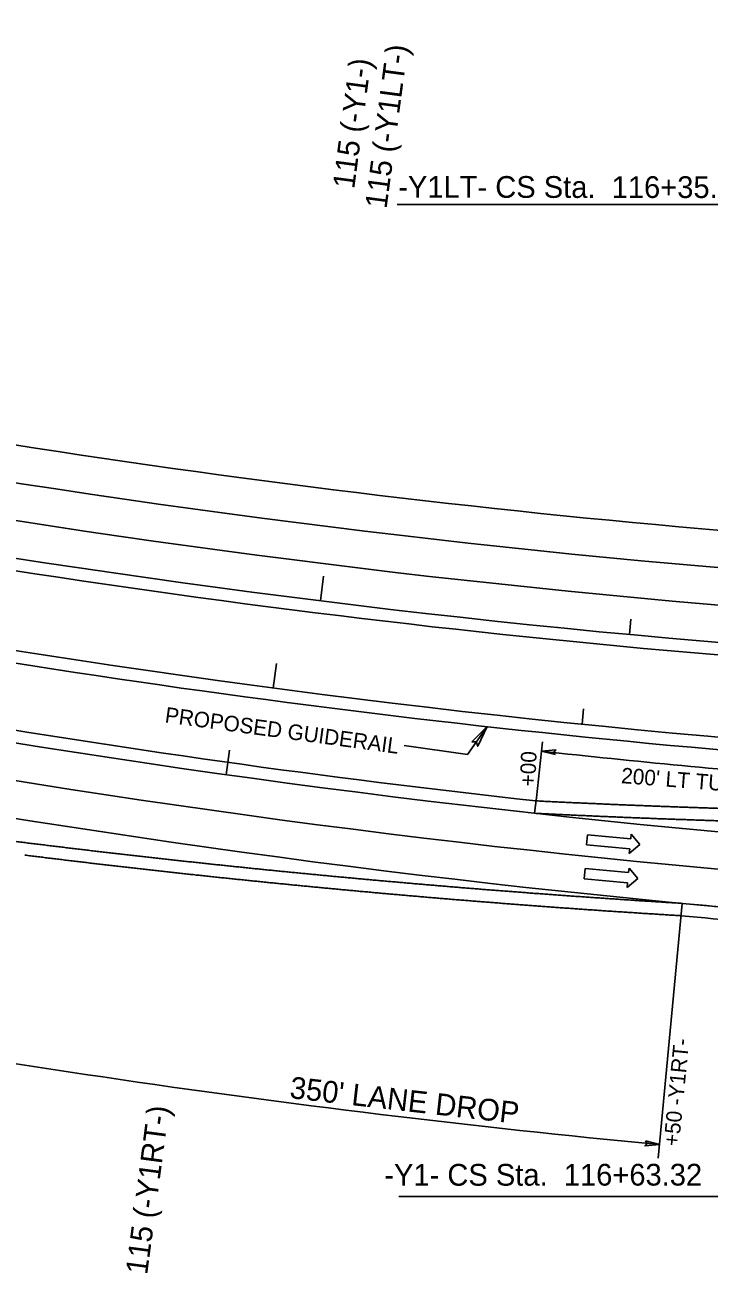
# Model space of a CAD drawing. Extents: x 2389694 to 2405615, y 547005 to 573532.
# Drawn here: x 2399293 to 2399513, y 552256.4 to 552658.1 of the extents above; entities that cross this region are included whole.
import ezdxf

# ---------------------------------------------------------------- set-up
doc = ezdxf.new("R2010")
doc.units = 0
for name, color, linetype in [('Old_Level_11', 7, 'Continuous'), ('Old_Level_22', 7, 'Continuous'), ('Prop Cable Guiderail Double Face', 7, 'Continuous'), ('Prop Dimension', 7, 'Continuous'), ('Prop Dimension Text', 7, 'Continuous'), ('Prop DSN Text', 7, 'Continuous'), ('Prop EOT', 7, 'Continuous'), ('Prop Horizontal Alignment', 7, 'Continuous'), ('Prop Horizontal Alignment Curve and Spiral Data', 7, 'Continuous'), ('Prop Horizontal Alignment Tick Large', 7, 'Continuous'), ('Prop Horizontal Alignment Tick Small', 7, 'Continuous'), ('Prop Lane Arrow Through CELL', 7, 'Continuous'), ('Prop Lane Lines', 7, 'Continuous')]:
    doc.layers.add(name, color=color, linetype=linetype)

# ---------------------------------------------------------------- blocks, each defined once
blk = doc.blocks.new('TERM')
at = {"layer": 'Old_Level_11'}
blk.add_lwpolyline([(-0.01375, 0.00225), (0, 0), (-0.01375, -0.0025), (-0.012, 0)], close=True, dxfattribs=at)

msp = doc.modelspace()

# ---------------------------------------------------------------- linework, layer by layer
at = {"layer": 'Prop Cable Guiderail Double Face'}
msp.add_arc((2399806.57, 555716.05), 3304, 257.63644, 265.28379, dxfattribs=at)
at = {"layer": 'Prop Dimension'}
for p, q in [((2399457.49, 552409.35), (2399459.48, 552427.43)), ((2399504.41, 552375.4), (2399496.65, 552293.39))]:
    msp.add_line(p, q, dxfattribs=at)
for points in [[(2399463.56, 552423.25), (2399459.14, 552424.39), (2399463.72, 552424.81), (2399463.08, 552424.06)], [(2399492.64, 552298.92), (2399497.06, 552297.77), (2399492.49, 552297.35), (2399493.12, 552298.1)]]:
    msp.add_lwpolyline(points, close=True, dxfattribs=at)
for radius, start, end in [(3302.88, 263.72437, 265.30001), (3424.97, 258.5517, 264.5865)]:
    msp.add_arc((2399820.18, 555707.47), radius, start, end, dxfattribs=at)
at = {"layer": 'Prop DSN Text'}
for p, q in [((2399435.38, 552423.31), (2399441.62, 552432.29)), ((2399414.97, 552426.15), (2399435.38, 552423.31))]:
    msp.add_line(p, q, dxfattribs=at)
at = {"layer": 'Prop EOT'}
for centre, radius, start, end in [((2399792.96, 555724.63), 3253, 240.16192, 265.26734), ((2399792.96, 555724.63), 3241, 256.84167, 265.26734), ((2399792.96, 555724.63), 3281, 256.78262, 265.26734), ((2399820.18, 555707.47), 3319, 256.69858, 263.72436), ((2399820.18, 555707.47), 3347, 264.58646, 265.30001), ((2399820.18, 555707.47), 3351, 264.58646, 265.30001)]:
    msp.add_arc(centre, radius, start, end, dxfattribs=at)
for points in [[(2399457.14, 552408.38), (2399458.04, 552408.34), (2399458.94, 552408.29), (2399459.84, 552408.25), (2399460.74, 552408.2), (2399461.64, 552408.16), (2399462.54, 552408.12), (2399463.44, 552408.07), (2399464.34, 552408.03), (2399465.24, 552407.99), (2399466.14, 552407.94), (2399467.04, 552407.9), (2399467.94, 552407.86), (2399468.84, 552407.82), (2399469.74, 552407.78), (2399470.64, 552407.74), (2399471.54, 552407.7), (2399472.45, 552407.65), (2399473.35, 552407.61), (2399474.25, 552407.57), (2399475.15, 552407.53), (2399476.04, 552407.5), (2399476.94, 552407.46), (2399477.84, 552407.42), (2399478.74, 552407.38), (2399479.64, 552407.34), (2399480.54, 552407.3), (2399481.44, 552407.26), (2399482.35, 552407.22), (2399483.25, 552407.19), (2399484.15, 552407.15), (2399485.05, 552407.11), (2399485.95, 552407.07), (2399486.85, 552407.04), (2399487.75, 552407), (2399488.65, 552406.97), (2399489.54, 552406.93), (2399490.44, 552406.89), (2399491.34, 552406.86), (2399492.25, 552406.82), (2399493.15, 552406.79), (2399494.05, 552406.75), (2399494.95, 552406.72), (2399495.85, 552406.68), (2399496.75, 552406.65), (2399497.65, 552406.62), (2399498.55, 552406.58), (2399499.45, 552406.55), (2399500.35, 552406.52), (2399501.25, 552406.48), (2399502.16, 552406.45), (2399503.05, 552406.42), (2399503.95, 552406.39), (2399504.85, 552406.36), (2399505.75, 552406.32), (2399506.65, 552406.29), (2399507.55, 552406.26), (2399508.45, 552406.23), (2399509.35, 552406.2), (2399510.25, 552406.17), (2399511.15, 552406.14), (2399512.05, 552406.11), (2399512.96, 552406.08), (2399513.85, 552406.05), (2399514.75, 552406.02), (2399515.65, 552405.99), (2399516.55, 552405.96), (2399517.45, 552405.94), (2399518.35, 552405.91), (2399519.25, 552405.88), (2399520.15, 552405.85), (2399521.05, 552405.83), (2399521.95, 552405.8), (2399522.86, 552405.77), (2399523.75, 552405.74)], [(2399223.4, 552404.35), (2399224.35, 552404.21), (2399225.29, 552404.08), (2399226.24, 552403.94), (2399227.18, 552403.8), (2399228.13, 552403.66), (2399229.08, 552403.53), (2399230.02, 552403.39), (2399230.97, 552403.25), (2399231.91, 552403.12), (2399232.86, 552402.98), (2399233.81, 552402.85), (2399234.75, 552402.71), (2399235.7, 552402.58), (2399236.64, 552402.45), (2399237.59, 552402.31), (2399238.54, 552402.18), (2399239.48, 552402.04), (2399240.43, 552401.91), (2399241.37, 552401.78), (2399242.32, 552401.65), (2399243.27, 552401.51), (2399244.22, 552401.38), (2399245.17, 552401.25), (2399246.11, 552401.12), (2399247.06, 552400.99), (2399248, 552400.86), (2399248.95, 552400.72), (2399249.9, 552400.59), (2399250.84, 552400.46), (2399251.79, 552400.33), (2399252.73, 552400.2), (2399253.68, 552400.07), (2399254.64, 552399.94), (2399255.58, 552399.82), (2399256.53, 552399.69), (2399257.47, 552399.56), (2399258.42, 552399.43), (2399259.37, 552399.3), (2399260.31, 552399.18), (2399261.26, 552399.05), (2399262.21, 552398.92), (2399263.16, 552398.79), (2399264.11, 552398.67), (2399265.05, 552398.54), (2399266, 552398.42), (2399266.94, 552398.29), (2399267.89, 552398.17), (2399268.84, 552398.04), (2399269.79, 552397.92), (2399270.74, 552397.79), (2399271.68, 552397.67), (2399272.63, 552397.54), (2399273.58, 552397.42), (2399274.52, 552397.3), (2399275.48, 552397.17), (2399276.42, 552397.05), (2399277.37, 552396.93), (2399278.31, 552396.8), (2399279.26, 552396.68), (2399280.21, 552396.56), (2399281.16, 552396.44), (2399282.11, 552396.32), (2399283.05, 552396.2), (2399284, 552396.08), (2399284.95, 552395.95), (2399285.9, 552395.84), (2399286.85, 552395.71), (2399287.79, 552395.6), (2399288.74, 552395.48), (2399289.69, 552395.36), (2399290.64, 552395.24), (2399291.59, 552395.12), (2399292.53, 552395), (2399293.48, 552394.88)], [(2399456.94, 552404.38), (2399457.84, 552404.34), (2399458.74, 552404.3), (2399459.64, 552404.25), (2399460.54, 552404.21), (2399461.44, 552404.16), (2399462.35, 552404.12), (2399463.25, 552404.08), (2399464.15, 552404.03), (2399465.05, 552403.99), (2399465.95, 552403.95), (2399466.85, 552403.91), (2399467.76, 552403.87), (2399468.66, 552403.82), (2399469.56, 552403.78), (2399470.46, 552403.74), (2399471.36, 552403.7), (2399472.27, 552403.66), (2399473.17, 552403.62), (2399474.07, 552403.58), (2399474.97, 552403.54), (2399475.87, 552403.5), (2399476.77, 552403.46), (2399477.67, 552403.42), (2399478.57, 552403.38), (2399479.47, 552403.34), (2399480.37, 552403.3), (2399481.27, 552403.27), (2399482.18, 552403.23), (2399483.08, 552403.19), (2399483.98, 552403.15), (2399484.88, 552403.12), (2399485.78, 552403.08), (2399486.68, 552403.04), (2399487.58, 552403.01), (2399488.49, 552402.97), (2399489.39, 552402.93), (2399490.29, 552402.9), (2399491.19, 552402.86), (2399492.1, 552402.83), (2399493, 552402.79), (2399493.9, 552402.76), (2399494.8, 552402.72), (2399495.7, 552402.69), (2399496.6, 552402.65), (2399497.5, 552402.62), (2399498.4, 552402.59), (2399499.3, 552402.55), (2399500.2, 552402.52), (2399501.1, 552402.49), (2399502.01, 552402.45), (2399502.91, 552402.42), (2399503.81, 552402.39), (2399504.71, 552402.36), (2399505.61, 552402.33), (2399506.51, 552402.3), (2399507.41, 552402.26), (2399508.31, 552402.23), (2399509.21, 552402.2), (2399510.11, 552402.17), (2399511.01, 552402.14), (2399511.91, 552402.11), (2399512.82, 552402.08), (2399513.72, 552402.05), (2399514.62, 552402.02), (2399515.52, 552401.99), (2399516.42, 552401.97), (2399517.33, 552401.94), (2399518.23, 552401.91), (2399519.13, 552401.88), (2399520.03, 552401.85), (2399520.93, 552401.83), (2399521.83, 552401.8), (2399522.74, 552401.77), (2399523.64, 552401.75)], [(2399293.48, 552394.88), (2399294.43, 552394.76), (2399295.38, 552394.65), (2399296.33, 552394.53), (2399297.27, 552394.41), (2399298.22, 552394.3), (2399299.17, 552394.18), (2399300.12, 552394.06), (2399301.07, 552393.95), (2399302.01, 552393.83), (2399302.96, 552393.72), (2399303.92, 552393.6), (2399304.86, 552393.49), (2399305.81, 552393.37), (2399306.75, 552393.26), (2399307.71, 552393.14), (2399308.66, 552393.03), (2399309.6, 552392.92), (2399310.55, 552392.8), (2399311.5, 552392.69), (2399312.45, 552392.58), (2399313.39, 552392.47), (2399314.34, 552392.35), (2399315.3, 552392.24), (2399316.24, 552392.13), (2399317.19, 552392.02), (2399318.14, 552391.91), (2399319.09, 552391.8), (2399320.04, 552391.69), (2399320.98, 552391.58), (2399321.94, 552391.47), (2399322.88, 552391.36), (2399323.83, 552391.25), (2399324.78, 552391.14), (2399325.73, 552391.03), (2399326.68, 552390.92), (2399327.62, 552390.81), (2399328.58, 552390.71), (2399329.53, 552390.6), (2399330.47, 552390.49), (2399331.43, 552390.38), (2399332.37, 552390.28), (2399333.32, 552390.17), (2399334.27, 552390.06), (2399335.22, 552389.96), (2399336.17, 552389.85), (2399337.11, 552389.75), (2399338.07, 552389.64), (2399339.02, 552389.54), (2399339.96, 552389.43), (2399340.92, 552389.33), (2399341.86, 552389.22), (2399342.81, 552389.12), (2399343.77, 552389.01), (2399344.71, 552388.91), (2399345.66, 552388.81), (2399346.61, 552388.71), (2399347.56, 552388.6), (2399348.5, 552388.5), (2399349.46, 552388.4), (2399350.41, 552388.3), (2399351.35, 552388.2), (2399352.31, 552388.09), (2399353.25, 552387.99), (2399354.2, 552387.89), (2399355.16, 552387.79), (2399356.1, 552387.69), (2399357.06, 552387.59), (2399358, 552387.49), (2399358.95, 552387.39), (2399359.91, 552387.29), (2399360.85, 552387.2), (2399361.8, 552387.1), (2399362.75, 552387), (2399363.7, 552386.9)], [(2399292.99, 552390.91), (2399293.94, 552390.8), (2399294.88, 552390.68), (2399295.84, 552390.56), (2399296.78, 552390.44), (2399297.73, 552390.33), (2399298.69, 552390.21), (2399299.63, 552390.09), (2399300.58, 552389.98), (2399301.53, 552389.86), (2399302.48, 552389.75), (2399303.44, 552389.63), (2399304.38, 552389.52), (2399305.33, 552389.4), (2399306.28, 552389.29), (2399307.23, 552389.17), (2399308.18, 552389.06), (2399309.13, 552388.95), (2399310.08, 552388.83), (2399311.02, 552388.72), (2399311.98, 552388.61), (2399312.92, 552388.5), (2399313.87, 552388.38), (2399314.83, 552388.27), (2399315.77, 552388.16), (2399316.73, 552388.05), (2399317.67, 552387.94), (2399318.62, 552387.83), (2399319.58, 552387.71), (2399320.52, 552387.6), (2399321.48, 552387.49), (2399322.42, 552387.39), (2399323.37, 552387.28), (2399324.33, 552387.17), (2399325.27, 552387.06), (2399326.23, 552386.95), (2399327.17, 552386.84), (2399328.12, 552386.73), (2399329.08, 552386.62), (2399330.02, 552386.52), (2399330.98, 552386.41), (2399331.92, 552386.3), (2399332.87, 552386.2), (2399333.83, 552386.09), (2399334.77, 552385.98), (2399335.73, 552385.88), (2399336.67, 552385.77), (2399337.63, 552385.67), (2399338.58, 552385.56), (2399339.53, 552385.46), (2399340.48, 552385.35), (2399341.42, 552385.25), (2399342.38, 552385.14), (2399343.33, 552385.04), (2399344.28, 552384.94), (2399345.23, 552384.83), (2399346.18, 552384.73), (2399347.13, 552384.63), (2399348.08, 552384.52), (2399349.03, 552384.42), (2399349.98, 552384.32), (2399350.93, 552384.22), (2399351.88, 552384.12), (2399352.83, 552384.02), (2399353.78, 552383.92), (2399354.74, 552383.81), (2399355.68, 552383.71), (2399356.64, 552383.61), (2399357.58, 552383.52), (2399358.54, 552383.42), (2399359.49, 552383.32), (2399360.44, 552383.22), (2399361.39, 552383.12), (2399362.34, 552383.02), (2399363.29, 552382.92)], [(2399363.7, 552386.9), (2399364.65, 552386.8), (2399365.6, 552386.71), (2399366.55, 552386.61), (2399367.5, 552386.51), (2399368.45, 552386.42), (2399369.4, 552386.32), (2399370.35, 552386.22), (2399371.3, 552386.13), (2399372.25, 552386.03), (2399373.2, 552385.94), (2399374.15, 552385.84), (2399375.1, 552385.75), (2399376.05, 552385.65), (2399376.99, 552385.56), (2399377.95, 552385.46), (2399378.9, 552385.37), (2399379.85, 552385.28), (2399380.8, 552385.18), (2399381.74, 552385.09), (2399382.7, 552385), (2399383.64, 552384.91), (2399384.6, 552384.82), (2399385.55, 552384.72), (2399386.5, 552384.63), (2399387.45, 552384.54), (2399388.39, 552384.45), (2399389.35, 552384.36), (2399390.3, 552384.27), (2399391.25, 552384.18), (2399392.2, 552384.09), (2399393.14, 552384), (2399394.1, 552383.91), (2399395.05, 552383.82), (2399396, 552383.73), (2399396.95, 552383.64), (2399397.9, 552383.56), (2399398.85, 552383.47), (2399399.81, 552383.38), (2399400.75, 552383.29), (2399401.7, 552383.21), (2399402.65, 552383.12), (2399403.6, 552383.03), (2399404.56, 552382.95), (2399405.5, 552382.86), (2399406.46, 552382.77), (2399407.4, 552382.69), (2399408.36, 552382.6), (2399409.31, 552382.52), (2399410.25, 552382.43), (2399411.21, 552382.35), (2399412.15, 552382.27), (2399413.11, 552382.18), (2399414.06, 552382.1), (2399415.01, 552382.02), (2399415.96, 552381.93), (2399416.91, 552381.85), (2399417.86, 552381.77), (2399418.81, 552381.69), (2399419.76, 552381.6), (2399420.72, 552381.52), (2399421.66, 552381.44), (2399422.61, 552381.36), (2399423.56, 552381.28), (2399424.51, 552381.2), (2399425.47, 552381.12), (2399426.41, 552381.04), (2399427.37, 552380.96), (2399428.31, 552380.88), (2399429.27, 552380.8), (2399430.22, 552380.72), (2399431.17, 552380.64), (2399432.12, 552380.56), (2399433.07, 552380.48), (2399434.02, 552380.41)], [(2399363.29, 552382.92), (2399364.25, 552382.82), (2399365.19, 552382.73), (2399366.15, 552382.63), (2399367.09, 552382.53), (2399368.04, 552382.44), (2399369, 552382.34), (2399369.95, 552382.24), (2399370.9, 552382.15), (2399371.85, 552382.05), (2399372.8, 552381.96), (2399373.76, 552381.86), (2399374.7, 552381.77), (2399375.66, 552381.67), (2399376.6, 552381.58), (2399377.56, 552381.48), (2399378.51, 552381.39), (2399379.46, 552381.3), (2399380.41, 552381.2), (2399381.36, 552381.11), (2399382.31, 552381.02), (2399383.26, 552380.93), (2399384.21, 552380.83), (2399385.17, 552380.74), (2399386.11, 552380.65), (2399387.07, 552380.56), (2399388.01, 552380.47), (2399388.97, 552380.38), (2399389.92, 552380.29), (2399390.87, 552380.2), (2399391.83, 552380.11), (2399392.77, 552380.02), (2399393.73, 552379.93), (2399394.68, 552379.84), (2399395.63, 552379.75), (2399396.58, 552379.66), (2399397.53, 552379.57), (2399398.48, 552379.48), (2399399.44, 552379.4), (2399400.38, 552379.31), (2399401.34, 552379.22), (2399402.29, 552379.14), (2399403.24, 552379.05), (2399404.2, 552378.96), (2399405.14, 552378.88), (2399406.1, 552378.79), (2399407.04, 552378.71), (2399408, 552378.62), (2399408.95, 552378.53), (2399409.9, 552378.45), (2399410.86, 552378.36), (2399411.8, 552378.28), (2399412.76, 552378.2), (2399413.71, 552378.11), (2399414.66, 552378.03), (2399415.61, 552377.95), (2399416.56, 552377.86), (2399417.52, 552377.78), (2399418.46, 552377.7), (2399419.42, 552377.62), (2399420.37, 552377.54), (2399421.32, 552377.45), (2399422.27, 552377.37), (2399423.22, 552377.29), (2399424.18, 552377.21), (2399425.13, 552377.13), (2399426.08, 552377.05), (2399427.03, 552376.97), (2399427.98, 552376.89), (2399428.94, 552376.81), (2399429.89, 552376.73), (2399430.84, 552376.65), (2399431.79, 552376.58), (2399432.74, 552376.5), (2399433.7, 552376.42)], [(2399434.02, 552380.41), (2399434.98, 552380.33), (2399435.92, 552380.25), (2399436.88, 552380.17), (2399437.82, 552380.1), (2399438.78, 552380.02), (2399439.73, 552379.94), (2399440.68, 552379.87), (2399441.63, 552379.79), (2399442.58, 552379.72), (2399443.53, 552379.64), (2399444.49, 552379.57), (2399445.43, 552379.49), (2399446.39, 552379.42), (2399447.33, 552379.35), (2399448.29, 552379.27), (2399449.24, 552379.2), (2399450.19, 552379.12), (2399451.14, 552379.05), (2399452.09, 552378.98), (2399453.04, 552378.91), (2399453.99, 552378.84), (2399454.94, 552378.76), (2399455.9, 552378.69), (2399456.84, 552378.62), (2399457.8, 552378.55), (2399458.74, 552378.48), (2399459.7, 552378.41), (2399460.65, 552378.34), (2399461.6, 552378.27), (2399462.55, 552378.2), (2399463.5, 552378.13), (2399464.46, 552378.06), (2399465.41, 552377.99), (2399466.36, 552377.92), (2399467.31, 552377.85), (2399468.26, 552377.79), (2399469.21, 552377.72), (2399470.17, 552377.65), (2399471.11, 552377.58), (2399472.07, 552377.52), (2399473.01, 552377.45), (2399473.97, 552377.38), (2399474.92, 552377.32), (2399475.87, 552377.25), (2399476.82, 552377.18), (2399477.77, 552377.12), (2399478.73, 552377.05), (2399479.68, 552376.99), (2399480.63, 552376.93), (2399481.58, 552376.86), (2399482.53, 552376.8), (2399483.48, 552376.73), (2399484.44, 552376.67), (2399485.38, 552376.61), (2399486.34, 552376.54), (2399487.28, 552376.48), (2399488.24, 552376.42), (2399489.19, 552376.36), (2399490.14, 552376.29), (2399491.1, 552376.23), (2399492.04, 552376.17), (2399493, 552376.11), (2399493.94, 552376.05), (2399494.9, 552375.99), (2399495.85, 552375.93), (2399496.8, 552375.87), (2399497.76, 552375.81), (2399498.7, 552375.75), (2399499.66, 552375.69), (2399500.61, 552375.63), (2399501.56, 552375.57), (2399502.51, 552375.52), (2399504.42, 552375.4)], [(2399433.7, 552376.42), (2399434.65, 552376.34), (2399435.6, 552376.27), (2399436.56, 552376.19), (2399437.5, 552376.11), (2399438.46, 552376.03), (2399439.41, 552375.96), (2399440.36, 552375.88), (2399441.31, 552375.81), (2399442.26, 552375.73), (2399443.22, 552375.66), (2399444.17, 552375.58), (2399445.12, 552375.51), (2399446.08, 552375.43), (2399447.02, 552375.36), (2399447.98, 552375.28), (2399448.93, 552375.21), (2399449.88, 552375.14), (2399450.84, 552375.06), (2399451.78, 552374.99), (2399452.74, 552374.92), (2399453.69, 552374.85), (2399454.64, 552374.77), (2399455.6, 552374.7), (2399456.54, 552374.63), (2399457.5, 552374.56), (2399458.45, 552374.49), (2399459.4, 552374.42), (2399460.36, 552374.35), (2399461.31, 552374.28), (2399462.26, 552374.21), (2399463.21, 552374.14), (2399464.17, 552374.07), (2399465.12, 552374), (2399466.07, 552373.93), (2399467.03, 552373.86), (2399467.97, 552373.8), (2399468.93, 552373.73), (2399469.89, 552373.66), (2399470.83, 552373.59), (2399471.79, 552373.53), (2399472.73, 552373.46), (2399473.69, 552373.39), (2399474.65, 552373.33), (2399475.59, 552373.26), (2399476.55, 552373.19), (2399477.5, 552373.13), (2399478.45, 552373.06), (2399479.41, 552373), (2399480.36, 552372.93), (2399481.31, 552372.87), (2399482.26, 552372.81), (2399483.22, 552372.74), (2399484.17, 552372.68), (2399485.12, 552372.62), (2399486.08, 552372.55), (2399487.02, 552372.49), (2399487.98, 552372.43), (2399488.93, 552372.37), (2399489.88, 552372.3), (2399490.84, 552372.24), (2399491.79, 552372.18), (2399492.74, 552372.12), (2399493.69, 552372.06), (2399494.65, 552372), (2399495.6, 552371.94), (2399496.55, 552371.88), (2399497.51, 552371.82), (2399498.45, 552371.76), (2399499.41, 552371.7), (2399500.37, 552371.64), (2399501.31, 552371.58), (2399502.27, 552371.52), (2399504.17, 552371.41)]]:
    msp.add_spline(points, degree=3, dxfattribs=at)
at = {"layer": 'Prop Horizontal Alignment'}
for centre, radius, start, end in [((2399792.96, 555724.63), 3277, 240.16192, 265.26734), ((2399806.57, 555716.05), 3300, 240.14547, 265.28379), ((2399820.18, 555707.47), 3323, 240.12925, 265.30001)]:
    msp.add_arc(centre, radius, start, end, dxfattribs=at)
at = {"layer": 'Prop Horizontal Alignment Curve and Spiral Data'}
for p, q in [((2399534.3, 552600.29), (2399412.68, 552600.29)), ((2399523.18, 552281), (2399413.27, 552281))]:
    msp.add_line(p, q, dxfattribs=at)
at = {"layer": 'Prop Horizontal Alignment Tick Large'}
for p, q in [((2399388.05, 552472.74), (2399389.04, 552480.68)), ((2399372.87, 552444.67), (2399373.92, 552452.6)), ((2399357.72, 552416.81), (2399358.83, 552424.73))]:
    msp.add_line(p, q, dxfattribs=at)
at = {"layer": 'Prop Horizontal Alignment Tick Small'}
for p, q in [((2399487.46, 552461.9), (2399487.92, 552466.88)), ((2399472.19, 552433.03), (2399472.7, 552438.01)), ((2399456.94, 552404.38), (2399457.49, 552409.35))]:
    msp.add_line(p, q, dxfattribs=at)
at = {"layer": 'Prop Lane Arrow Through CELL'}
for p, q in [((2399473.59, 552394.2), (2399473.9, 552397.49)), ((2399473.9, 552397.49), (2399487.84, 552396.19)), ((2399487.84, 552396.19), (2399487.98, 552397.68)), ((2399487.98, 552397.68), (2399490.83, 552394.3)), ((2399487.53, 552392.9), (2399473.59, 552394.2)), ((2399490.83, 552394.3), (2399487.39, 552391.41)), ((2399487.39, 552391.41), (2399487.53, 552392.9)), ((2399472.92, 552383.29), (2399473.23, 552386.57)), ((2399473.23, 552386.57), (2399487.17, 552385.28)), ((2399487.17, 552385.28), (2399487.31, 552386.77)), ((2399487.31, 552386.77), (2399490.15, 552383.39)), ((2399486.86, 552381.99), (2399472.92, 552383.29)), ((2399490.15, 552383.39), (2399486.72, 552380.5)), ((2399486.72, 552380.5), (2399486.86, 552381.99))]:
    msp.add_line(p, q, dxfattribs=at)
at = {"layer": 'Prop Lane Lines'}
for centre, radius, start, end in [((2399792.96, 555724.63), 3265, 240.16192, 265.26734), ((2399820.18, 555707.47), 3335, 240.12925, 265.30001), ((2399820.18, 555707.47), 3347, 240.12925, 265.30001)]:
    msp.add_arc(centre, radius, start, end, dxfattribs=at)

# ---------------------------------------------------------------- block references
at = {"layer": 'Prop DSN Text', "xscale": 499.99999999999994, "yscale": 499.99999999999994, "rotation": 54.65068674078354}
msp.add_blockref('TERM', (2399441.62, 552432.29), dxfattribs=at)

# ---------------------------------------------------------------- texts
at = {"layer": 'Old_Level_22'}
msp.add_text("350' LANE DROP", height=7, rotation=353.5464, dxfattribs=at).set_placement((2399377.93, 552312.73))
at = {"layer": 'Prop Dimension Text'}
for s, rotation, p in [('+00', 87.7549, (2399457.15, 552412.95)), ("200' LT TURN TAPER", 355.5943, (2399484.64, 552414.1)), ('+50 -Y1RT-', 84.427, (2399503.34, 552297.1))]:
    msp.add_text(s, height=5, rotation=rotation, dxfattribs=at).set_placement(p)
at = {"layer": 'Prop DSN Text'}
msp.add_text('PROPOSED GUIDERAIL', height=5, rotation=352.2895, dxfattribs=at).set_placement((2399337.8, 552433.66))
at = {"layer": 'Prop Horizontal Alignment Curve and Spiral Data'}
for s, rotation, p in [('115 (-Y1LT-)', 82.4481, (2399409.29, 552598.74)), ('115 (-Y1-)', 82.4481, (2399398.89, 552605.13)), ('-Y1LT- CS Sta.  116+35.27', 359.9463, (2399413.06, 552602.49)), ('115 (-Y1RT-)', 82.4481, (2399332.28, 552255.71)), ('-Y1- CS Sta.  116+63.32', 0.0436, (2399408.58, 552284.5))]:
    msp.add_text(s, height=7, rotation=rotation, dxfattribs=at).set_placement(p)

doc.saveas('drawing.dxf')
